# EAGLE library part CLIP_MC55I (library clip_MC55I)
clip pro MC55I
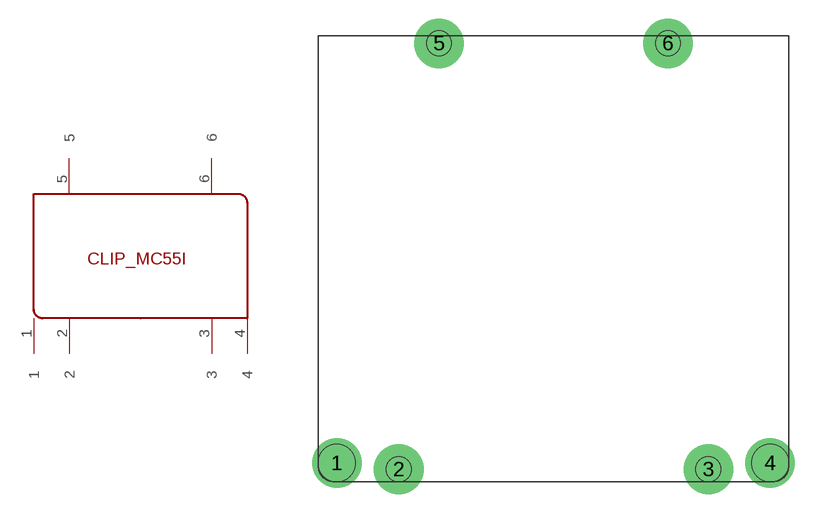
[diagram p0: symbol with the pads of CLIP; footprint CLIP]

Designator prefix -

## CLIP_MC55I  [CLIP]
1  1  nc
2  2  nc
3  3  nc
4  4  nc
5  5  nc
6  6  nc

## Footprint CLIP (pad centres in mm)
drill 2 pad 4 round: 1 0,0; 2 5,-0.5; 3 30,-0.5; 4 35,0; 5 8.25,33.9; 6 26.75,33.9
hole 2 at 8.25,33.9
hole 2 at 26.75,33.9
hole 3 at 0,0
hole 2 at 5,-0.5
hole 2 at 30,-0.5
hole 3 at 35,0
